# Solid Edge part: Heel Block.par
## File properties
Author: davee
Template: Normal.par
Last saved by: davee
Revision: 9
Application: Solid Edge
Accuracy: 0.990
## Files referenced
..\Loose Support Mould.asm
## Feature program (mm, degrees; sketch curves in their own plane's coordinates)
sketch for "unnamed Protrusion 1" plane through (0, 0, 0) normal (0, 0, 1) x-axis (1, 0, 0)
  line (-45.684, -27.536) -> (19.316, -27.536)
  line (19.316, -27.536) -> (19.316, 22.464)
  line (19.316, 22.464) -> (-45.684, 22.464)
  line (-45.684, 22.464) -> (-45.684, -27.536)
  dimension (linear) = 19.316
  dimension (linear) = 45.684
extrude "unnamed Protrusion 1" add finite 75 along -normal
sketch for "ExtrudedCutout_1" plane through (0, 0, 0) normal (1, 0, 0) x-axis (0, 1, 0)
extrude "ExtrudedCutout_1" cut finite 127 symmetric
sketch for "unnamed Cutout 1" plane through (-13.184, 0.6985, 0) normal (0, 0, 1) x-axis (0, 1, 0)
  line (-28.2345, 14.9581) -> (-28.2345, -14.9581)
extrude "unnamed Cutout 1" cut through along -normal
sketch for "ExtrudedProtrusion_2" plane through (-13.184, 22.464, -30) normal (0, 1, 0) x-axis (-1, 0, 0)
  line (-32.5, -45) -> (-32.5, 30)
  line (-32.5, 30) -> (32.5, 30)
  line (32.5, -45) -> (32.5, 30)
  line (-32.5, -45) -> (32.5, -45)
extrude "ExtrudedProtrusion_2" add finite 29.5 along +normal
sketch for "Hole_1" plane through (-13.184, 15.4485, 0) normal (0, 0, 1) x-axis (0, 1, 0)
  hole centre (0.0155, -20) bore radius 5.25
hole "Hole_1" diameter 10.5 through  CounterBoreDepth = 10.5 mm; VBottomAngle = 118 deg
sketch for "unnamed Hole 1" plane through (-13.184, 15.4485, 0) normal (0, 0, 1) x-axis (0, 1, 0)
  hole centre (0.0155, 20) bore radius 5.25
hole "unnamed Hole 1" through
pattern "unnamed Pattern 1" of "Hole_1", "unnamed Hole 1"
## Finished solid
Body 1: solid body, 16 faces, 32 edges, 16 vertices.
  Faces by surface: plane 11, cylinder 5
  Edges by curve: line 22, circle 9, ellipse 1
Bounding box of the edges (mm): 65.000 x 79.500 x 75.000, from (-45.684, -27.536, -75) to (19.316, 51.964, 0).
Cylindrical faces by radius (mm): R5.25 x2, R8.5 x2, R15 x1
Planar faces by outward normal: +x 1, +y 1, +z 3, -x 1, -y 3, -z 1, oblique 1
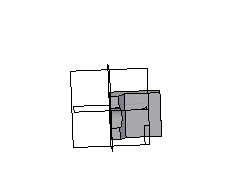
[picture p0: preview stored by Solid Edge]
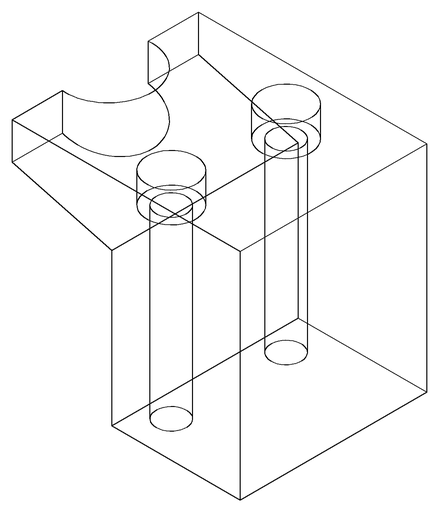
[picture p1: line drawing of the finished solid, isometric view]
